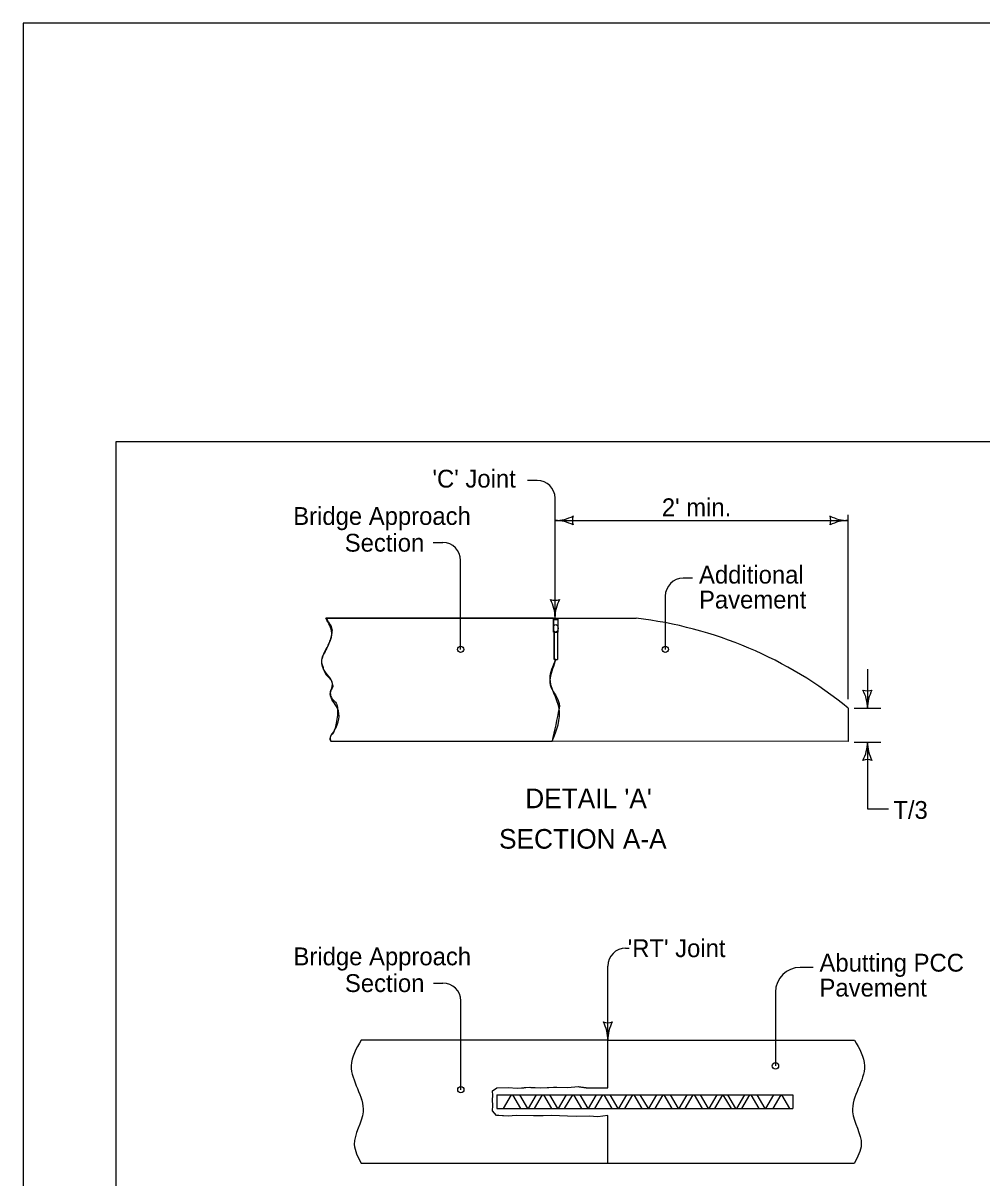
# Model space of a CAD drawing. Extents: x -2135039 to -2131695, y -2139150 to -2136566.
# Drawn here: x -2135039 to -2133963, y -2137862 to -2136566 of the extents above; entities that cross this region are included whole.
import ezdxf

# ---------------------------------------------------------------- set-up
doc = ezdxf.new("R2010")
doc.units = 0
for name, color, linetype in [('dsnCellElements', 7, 'Continuous'), ('dsnDOTLogo', 7, 'Continuous'), ('Level 1', 7, 'Continuous'), ('Level 2', 7, 'Continuous'), ('Level 3', 7, 'Continuous')]:
    doc.layers.add(name, color=color, linetype=linetype)

msp = doc.modelspace()

# ---------------------------------------------------------------- linework, layer by layer
at = {"layer": 'dsnCellElements'}
msp.add_circle((-2134194.9, -2137736.7), 3.54, dxfattribs=at)
at = {"layer": 'dsnDOTLogo'}
msp.add_lwpolyline([(-2135038.9, -2139150.4), (-2131694.9, -2139150.4), (-2131694.9, -2136566.4), (-2135038.9, -2136566.4)], close=True, dxfattribs=at)
at = {"layer": 'Level 1'}
msp.add_lwpolyline([(-2134934.4, -2137035.9), (-2131799.4, -2137035.9), (-2131799.4, -2139045.9), (-2134934.4, -2139045.9)], close=True, dxfattribs=at)
at = {"layer": 'Level 2'}
for p, q in [((-2134462.2, -2137079.6), (-2134473, -2137079.6)), ((-2134442.2, -2137233.7), (-2134442.2, -2137099.6)), ((-2134113.3, -2137325), (-2134113.3, -2137118.1)), ((-2134442.2, -2137124.6), (-2134113.3, -2137124.6)), ((-2134578.9, -2137149.4), (-2134568.1, -2137149.4)), ((-2134548.1, -2137269.3), (-2134548.1, -2137169.4)), ((-2134287.9, -2137189.4), (-2134298.5, -2137189.4)), ((-2134318.5, -2137209.4), (-2134318.5, -2137269.3)), ((-2134699.3, -2137234.3), (-2134441.4, -2137234.3)), ((-2134687.2, -2137234.3), (-2134699.3, -2137234.3)), ((-2134699.3, -2137234.3), (-2134697.4, -2137236.9)), ((-2134652.1, -2137234.3), (-2134685.7, -2137234.3)), ((-2134617, -2137234.3), (-2134650.5, -2137234.3)), ((-2134581.8, -2137234.3), (-2134615.4, -2137234.3)), ((-2134511.6, -2137234.3), (-2134545.2, -2137234.3)), ((-2134476.5, -2137234.3), (-2134510.1, -2137234.3)), ((-2134444, -2137234.3), (-2134475, -2137234.3)), ((-2134444, -2137234.3), (-2134444, -2137249.9)), ((-2134441.4, -2137234.3), (-2134351.1, -2137234.3)), ((-2134438.8, -2137249.9), (-2134438.8, -2137234.3)), ((-2134444, -2137235.9), (-2134438.8, -2137235.9)), ((-2134444, -2137249.9), (-2134438.8, -2137249.9)), ((-2134443.1, -2137249.9), (-2134444, -2137249.9)), ((-2134443.1, -2137249.9), (-2134443.1, -2137280.8)), ((-2134443.1, -2137280.8), (-2134443.1, -2137249.9)), ((-2134439.6, -2137249.9), (-2134439.6, -2137280.8)), ((-2134443.1, -2137280.8), (-2134439.6, -2137280.8)), ((-2134441.4, -2137280.8), (-2134443.1, -2137280.8)), ((-2134091.7, -2137291.5), (-2134091.7, -2137335.3)), ((-2134113.3, -2137335.3), (-2134113.3, -2137372.6)), ((-2134106.7, -2137335.3), (-2134076.7, -2137335.3)), ((-2134113.3, -2137372.6), (-2134693.9, -2137372.2)), ((-2134693.9, -2137372.2), (-2134445.5, -2137372.4)), ((-2134106.7, -2137373.5), (-2134076.7, -2137373.5)), ((-2134091.7, -2137373.5), (-2134091.7, -2137448.1)), ((-2134091.7, -2137448.1), (-2134068.2, -2137448.1)), ((-2134363, -2137604.6), (-2134359.1, -2137604.6)), ((-2134383, -2137707.7), (-2134383, -2137624.6)), ((-2134152.6, -2137626.2), (-2134167.2, -2137626.2)), ((-2134578.6, -2137643.7), (-2134567.9, -2137643.7)), ((-2134194.9, -2137653.9), (-2134194.9, -2137736.7)), ((-2134547.9, -2137763.5), (-2134547.9, -2137663.7)), ((-2134383, -2137707.7), (-2134659.6, -2137707.7)), ((-2134383, -2137707.7), (-2134106.4, -2137707.7)), ((-2134383, -2137761.5), (-2134383, -2137707.7)), ((-2134383, -2137761.5), (-2134383, -2137707.7)), ((-2134507.4, -2137769.1), (-2134175.5, -2137769.1)), ((-2134507.4, -2137769.1), (-2134507.4, -2137784.6)), ((-2134175.5, -2137769.1), (-2134175.5, -2137784.6)), ((-2134507.4, -2137784.6), (-2134175.5, -2137784.6)), ((-2134383, -2137846), (-2134383, -2137792.3)), ((-2134383, -2137846), (-2134383, -2137792.3)), ((-2134659.6, -2137846), (-2134374, -2137846)), ((-2134651.6, -2137846), (-2134651.6, -2137846)), ((-2134651.6, -2137846), (-2134618, -2137846)), ((-2134374, -2137846), (-2134106.4, -2137846))]:
    msp.add_line(p, q, dxfattribs=at)
for points in [[(-2134687.2, -2137234.3), (-2134687.2, -2137234.3)], [(-2134685.7, -2137234.3), (-2134685.7, -2137234.3)], [(-2134652.1, -2137234.3), (-2134652.1, -2137234.3)], [(-2134650.5, -2137234.3), (-2134650.5, -2137234.3)], [(-2134617, -2137234.3), (-2134617, -2137234.3)], [(-2134615.4, -2137234.3), (-2134615.4, -2137234.3)], [(-2134581.8, -2137234.3), (-2134581.8, -2137234.3)], [(-2134546.7, -2137234.3), (-2134548.1, -2137234.3), (-2134580.3, -2137234.3)], [(-2134580.3, -2137234.3), (-2134580.3, -2137234.3)], [(-2134546.7, -2137234.3), (-2134546.7, -2137234.3)], [(-2134545.2, -2137234.3), (-2134545.2, -2137234.3)], [(-2134511.6, -2137234.3), (-2134511.6, -2137234.3)], [(-2134510.1, -2137234.3), (-2134510.1, -2137234.3)], [(-2134476.5, -2137234.3), (-2134476.5, -2137234.3)], [(-2134475, -2137234.3), (-2134475, -2137234.3)], [(-2134444, -2137249.9), (-2134444, -2137235.9), (-2134444, -2137234.3)], [(-2134441.4, -2137280.8), (-2134441.4, -2137280.8)], [(-2134383, -2137707.7), (-2134468.4, -2137707.7), (-2134547.9, -2137707.7), (-2134605.4, -2137707.7), (-2134659.6, -2137707.7)], [(-2134383, -2137707.7), (-2134383, -2137707.7)], [(-2134507.7, -2137792.2), (-2134512.2, -2137787.2), (-2134511.9, -2137781), (-2134512.3, -2137774.9), (-2134511.9, -2137769.8), (-2134512.5, -2137764.7), (-2134507.6, -2137761.5)], [(-2134507.7, -2137792.2), (-2134512.2, -2137787.2), (-2134511.9, -2137781), (-2134512.3, -2137774.9), (-2134511.9, -2137769.8), (-2134512.5, -2137764.7), (-2134507.6, -2137761.5)], [(-2134507.6, -2137761.5), (-2134494.9, -2137760.9), (-2134484.6, -2137761.6), (-2134470.6, -2137760.7), (-2134458, -2137761.4), (-2134440.3, -2137760.5), (-2134427.9, -2137760.8), (-2134416.1, -2137760), (-2134404.4, -2137761.5), (-2134392.6, -2137761.4), (-2134382.9, -2137761.5)], [(-2134507.6, -2137761.5), (-2134494.9, -2137760.9), (-2134484.6, -2137761.6), (-2134479.9, -2137761.3), (-2134479.9, -2137761.3)], [(-2134475.1, -2137761), (-2134475.1, -2137761), (-2134470.6, -2137760.7), (-2134469.5, -2137760.8), (-2134469.5, -2137760.8), (-2134458, -2137761.4), (-2134443.9, -2137760.7), (-2134443.9, -2137760.7)], [(-2134440.5, -2137760.5), (-2134440.5, -2137760.5), (-2134440.3, -2137760.5), (-2134427.9, -2137760.8), (-2134416.1, -2137760), (-2134415.1, -2137760.2), (-2134415.1, -2137760.2), (-2134409.7, -2137760.8), (-2134409.3, -2137760.9)], [(-2134409.3, -2137760.9), (-2134409.3, -2137760.9)], [(-2134404.6, -2137761.5), (-2134404.4, -2137761.5), (-2134392.6, -2137761.4), (-2134383, -2137761.5)], [(-2134404.6, -2137761.5), (-2134404.6, -2137761.5)], [(-2134383, -2137761.5), (-2134383, -2137761.5)], [(-2134660.3, -2137774.3), (-2134660.4, -2137774.3)], [(-2134500, -2137784.6), (-2134491, -2137769.1)], [(-2134490, -2137769.1), (-2134481.1, -2137784.6)], [(-2134482.1, -2137769.1), (-2134473.1, -2137784.6)], [(-2134472.1, -2137784.6), (-2134463.1, -2137769.1)], [(-2134465.2, -2137784.6), (-2134456.2, -2137769.1)], [(-2134455.2, -2137769.1), (-2134446.2, -2137784.6)], [(-2134448.3, -2137769.1), (-2134439.3, -2137784.6)], [(-2134438.3, -2137784.6), (-2134429.3, -2137769.1)], [(-2134431.4, -2137784.6), (-2134422.4, -2137769.1)], [(-2134421.4, -2137769.1), (-2134412.4, -2137784.6)], [(-2134414.5, -2137769.1), (-2134405.5, -2137784.6)], [(-2134404.5, -2137784.6), (-2134395.5, -2137769.1)], [(-2134397.6, -2137784.6), (-2134388.6, -2137769.1)], [(-2134387.6, -2137769.1), (-2134378.6, -2137784.6)], [(-2134380.7, -2137769.1), (-2134371.7, -2137784.6)], [(-2134370.7, -2137784.6), (-2134361.7, -2137769.1)], [(-2134363.8, -2137784.6), (-2134354.8, -2137769.1)], [(-2134353.8, -2137769.1), (-2134344.8, -2137784.6)], [(-2134346.9, -2137769.1), (-2134337.9, -2137784.6)], [(-2134336.9, -2137784.6), (-2134327.9, -2137769.1)], [(-2134330, -2137784.6), (-2134321, -2137769.1)], [(-2134320, -2137769.1), (-2134311, -2137784.6)], [(-2134313.1, -2137769.1), (-2134304.1, -2137784.6)], [(-2134303.1, -2137784.6), (-2134294.1, -2137769.1)], [(-2134296.2, -2137784.6), (-2134287.2, -2137769.1)], [(-2134286.2, -2137769.1), (-2134277.2, -2137784.6)], [(-2134279.3, -2137769.1), (-2134270.3, -2137784.6)], [(-2134269.3, -2137784.6), (-2134260.3, -2137769.1)], [(-2134254.4, -2137769.1), (-2134263.4, -2137784.6)], [(-2134244.4, -2137784.6), (-2134253.4, -2137769.1)], [(-2134239.5, -2137784.6), (-2134248.5, -2137769.1)], [(-2134229.5, -2137769.1), (-2134238.5, -2137784.6)], [(-2134232.6, -2137784.6), (-2134223.6, -2137769.1)], [(-2134222.6, -2137769.1), (-2134213.6, -2137784.6)], [(-2134215.7, -2137769.1), (-2134206.7, -2137784.6)], [(-2134205.7, -2137784.6), (-2134196.7, -2137769.1)], [(-2134188.8, -2137769.1), (-2134197.8, -2137784.6)], [(-2134178.9, -2137784.6), (-2134187.8, -2137769.1)], [(-2134383, -2137792.3), (-2134394.2, -2137793.8), (-2134404, -2137793.2), (-2134418, -2137793.6), (-2134428.1, -2137793.2), (-2134446.2, -2137792.5), (-2134464, -2137792.9), (-2134485.7, -2137792.5), (-2134494.9, -2137793), (-2134507.7, -2137792.2)], [(-2134466.4, -2137792.9), (-2134466.4, -2137792.9), (-2134485.7, -2137792.5), (-2134494.9, -2137793), (-2134505.1, -2137792.4), (-2134505.1, -2137792.4), (-2134507.7, -2137792.2)], [(-2134383, -2137792.3), (-2134394.2, -2137793.8), (-2134404, -2137793.2), (-2134418, -2137793.6), (-2134428.1, -2137793.2), (-2134446.2, -2137792.5), (-2134455.5, -2137792.7), (-2134455.5, -2137792.7), (-2134461.5, -2137792.9), (-2134461.5, -2137792.9)], [(-2134659.6, -2137846), (-2134653.1, -2137846), (-2134653.1, -2137846)], [(-2134616.5, -2137846), (-2134616.5, -2137846)], [(-2134616.5, -2137846), (-2134604.9, -2137846), (-2134582.9, -2137846), (-2134582.9, -2137846)], [(-2134581.4, -2137846), (-2134581.4, -2137846), (-2134547.8, -2137846), (-2134547.8, -2137846)], [(-2134546.3, -2137846), (-2134546.3, -2137846), (-2134512.7, -2137846), (-2134512.7, -2137846)], [(-2134511.2, -2137846), (-2134511.2, -2137846), (-2134477.6, -2137846), (-2134477.6, -2137846)], [(-2134476.1, -2137846), (-2134476.1, -2137846), (-2134467.9, -2137846), (-2134442.5, -2137846), (-2134442.5, -2137846)], [(-2134441, -2137846), (-2134441, -2137846), (-2134407.4, -2137846), (-2134407.4, -2137846)], [(-2134405.9, -2137846), (-2134405.9, -2137846), (-2134383, -2137846)], [(-2134383, -2137846), (-2134383, -2137846)]]:
    msp.add_lwpolyline(points, dxfattribs=at)
for centre in [(-2134548.1, -2137269.3), (-2134548.1, -2137269.3), (-2134318.5, -2137269.3), (-2134547.9, -2137763.5), (-2134547.9, -2137763.5)]:
    msp.add_circle(centre, 3.5, dxfattribs=at)
for centre, radius, start, end in [((-2134462.2, -2137099.6), 20, 0, 90), ((-2134442.2, -2137081.5), 43.2, 270, 298.0725), ((-2134442.2, -2137081.5), 43.2, 270, 298.0725), ((-2134442.2, -2137167.8), 43.2, 61.9275, 90), ((-2134442.2, -2137167.8), 43.2, 61.9275, 90), ((-2134406, -2137124.6), 16.7, 162.2666, 197.7334), ((-2134406, -2137124.6), 16.7, 162.2666, 197.7334), ((-2134149.5, -2137124.6), 16.7, 342.2666, 17.7333), ((-2134113.3, -2137081.5), 43.2, 241.9275, 270), ((-2134113.3, -2137167.8), 43.2, 90, 118.0725), ((-2134568.1, -2137169.4), 20, 0, 90), ((-2134298.5, -2137209.4), 20, 90, 180), ((-2134442.2, -2137197.5), 16.7, 252.2666, 287.7333), ((-2134485.4, -2137233.7), 43.2, 360, 28.0725), ((-2134399.1, -2137233.7), 43.2, 151.9275, 180), ((-2134404.5, -2137690.6), 459.4, 50.6582, 83.3286), ((-2134091.7, -2137299.1), 16.7, 252.2666, 287.7333), ((-2134134.9, -2137335.3), 43.2, 360, 28.0725), ((-2134048.5, -2137335.3), 43.2, 151.9275, 180), ((-2134134.9, -2137373.5), 43.2, 331.9275, 360), ((-2134048.5, -2137373.5), 43.2, 180, 208.0725), ((-2134091.7, -2137409.7), 16.7, 72.2666, 107.7334), ((-2134363, -2137624.6), 20, 90, 180), ((-2134167.2, -2137653.9), 27.7, 90, 180), ((-2134567.9, -2137663.7), 20, 0, 90), ((-2134383, -2137671.5), 16.7, 252.2666, 287.7333), ((-2134426.1, -2137707.7), 43.2, 360, 28.0725), ((-2134339.8, -2137707.7), 43.2, 151.9275, 180), ((-2134339.8, -2137707.7), 43.2, 179.9993, 180)]:
    msp.add_arc(centre, radius, start, end, dxfattribs=at)
msp.add_ellipse((-2134441.4, -2137245.6), major_axis=(0, 4.37), ratio=0.6, dxfattribs=at)
for points in [[(-2134693.8, -2137372.3), (-2134694.3, -2137370.6), (-2134689.6, -2137359.9), (-2134686.3, -2137335.3), (-2134694.3, -2137319.2), (-2134691.9, -2137308.4), (-2134701.9, -2137291.5), (-2134703.5, -2137279.2), (-2134698.9, -2137269.2), (-2134692.7, -2137250.8), (-2134699.3, -2137234.3)], [(-2134441.4, -2137280.8), (-2134447.7, -2137301.8), (-2134447.9, -2137302.8), (-2134448.1, -2137303.9), (-2134448.1, -2137306), (-2134447.2, -2137310.1), (-2134443, -2137318.4), (-2134438.6, -2137326.8), (-2134437.5, -2137331), (-2134437.3, -2137333.1), (-2134437.4, -2137334.2), (-2134437.6, -2137335.3), (-2134445.5, -2137372.4)], [(-2134445.5, -2137372.4), (-2134437.6, -2137335.3), (-2134447.7, -2137301.8), (-2134441.4, -2137280.8)], [(-2134659.6, -2137707.7), (-2134670.9, -2137736.5), (-2134657.5, -2137788.3), (-2134667.4, -2137824.9), (-2134659.6, -2137846)], [(-2134659.6, -2137707.7), (-2134670.9, -2137736.5), (-2134657.5, -2137788.3), (-2134667.4, -2137824.9), (-2134659.6, -2137846)], [(-2134106.4, -2137707.7), (-2134095, -2137736.5), (-2134108.4, -2137788.3), (-2134098.6, -2137824.9), (-2134106.4, -2137846)]]:
    msp.add_spline(points, degree=3, dxfattribs=at)
for points, degree in [([(-2134685.7, -2137234.3), (-2134686.1, -2137234.3), (-2134686.7, -2137234.3), (-2134687.2, -2137234.3)], 2), ([(-2134650.5, -2137234.3), (-2134651, -2137234.3), (-2134651.5, -2137234.3), (-2134652.1, -2137234.3)], 2), ([(-2134615.4, -2137234.3), (-2134615.9, -2137234.3), (-2134616.4, -2137234.3), (-2134617, -2137234.3)], 2), ([(-2134580.3, -2137234.3), (-2134580.8, -2137234.3), (-2134581.3, -2137234.3), (-2134581.8, -2137234.3)], 2), ([(-2134545.2, -2137234.3), (-2134545.7, -2137234.3), (-2134546.2, -2137234.3), (-2134546.7, -2137234.3)], 2), ([(-2134510.1, -2137234.3), (-2134510.6, -2137234.3), (-2134511.1, -2137234.3), (-2134511.6, -2137234.3)], 2), ([(-2134475, -2137234.3), (-2134475.5, -2137234.3), (-2134476, -2137234.3), (-2134476.5, -2137234.3)], 2), ([(-2134695.9, -2137239.1), (-2134693.5, -2137242.9), (-2134692, -2137246.8), (-2134692.7, -2137250.8), (-2134693.8, -2137256.9), (-2134696.4, -2137263.1), (-2134698.9, -2137269.2), (-2134700.2, -2137272.7), (-2134702.4, -2137275.8), (-2134703.5, -2137279.2), (-2134704.7, -2137283.1), (-2134703.1, -2137287.6), (-2134701.9, -2137291.5), (-2134700, -2137297.6), (-2134693.5, -2137302.3), (-2134691.9, -2137308.4), (-2134691.1, -2137311.8), (-2134694.8, -2137315.7), (-2134694.3, -2137319.2), (-2134693.3, -2137324.8), (-2134686.5, -2137329.6), (-2134686.3, -2137335.3), (-2134686.1, -2137343.1), (-2134687.5, -2137352.1), (-2134689.6, -2137359.9), (-2134690.7, -2137363.6), (-2134695.1, -2137366.8), (-2134694.3, -2137370.6), (-2134694.1, -2137371.2), (-2134694, -2137371.7), (-2134693.9, -2137372.2)], 3), ([(-2134697.4, -2137236.9), (-2134697.1, -2137237.1), (-2134696.5, -2137237.8), (-2134696.1, -2137238.6), (-2134695.9, -2137239.1)], 3), ([(-2134479.9, -2137761.3), (-2134479.2, -2137761.3), (-2134478.4, -2137761.2), (-2134477.4, -2137761.2), (-2134476.1, -2137761.1), (-2134475.1, -2137761)], 3), ([(-2134443.9, -2137760.7), (-2134443.3, -2137760.7), (-2134442.6, -2137760.6), (-2134441.3, -2137760.5), (-2134440.5, -2137760.5)], 3), ([(-2134409.3, -2137760.9), (-2134408.4, -2137761), (-2134407.7, -2137761.1), (-2134406.8, -2137761.2), (-2134405.9, -2137761.3), (-2134404.6, -2137761.5)], 3), ([(-2134461.5, -2137792.9), (-2134463, -2137792.9), (-2134464, -2137792.9), (-2134465.5, -2137792.9), (-2134466.4, -2137792.9)], 3), ([(-2134653.1, -2137846), (-2134652.6, -2137845.9), (-2134652.1, -2137845.9), (-2134651.6, -2137846)], 2), ([(-2134618, -2137846), (-2134617.5, -2137845.9), (-2134617, -2137845.9), (-2134616.5, -2137846)], 2), ([(-2134618, -2137846), (-2134617.5, -2137845.9), (-2134617, -2137845.9), (-2134616.5, -2137846)], 2), ([(-2134582.9, -2137846), (-2134582.4, -2137845.9), (-2134581.8, -2137845.9), (-2134581.4, -2137846)], 2), ([(-2134547.8, -2137846), (-2134547.3, -2137845.9), (-2134546.7, -2137845.9), (-2134546.3, -2137846)], 2), ([(-2134512.7, -2137846), (-2134512.2, -2137845.9), (-2134511.6, -2137845.9), (-2134511.2, -2137846)], 2), ([(-2134477.6, -2137846), (-2134477.1, -2137845.9), (-2134476.5, -2137845.9), (-2134476.1, -2137846)], 2), ([(-2134442.5, -2137846), (-2134442, -2137845.9), (-2134441.4, -2137845.9), (-2134441, -2137846)], 2), ([(-2134407.4, -2137846), (-2134406.8, -2137845.9), (-2134406.3, -2137845.9), (-2134405.9, -2137846)], 2)]:
    msp.add_open_spline(points, degree=degree, dxfattribs=at)

# ---------------------------------------------------------------- texts
at = {"layer": 'Level 3'}
for s, height, p in [("'C' Joint", 20, (-2134579.7, -2137087.7)), ("2' min.", 20, (-2134322.4, -2137119.8)), ('Bridge Approach', 20, (-2134735.9, -2137129.6)), ('Section', 20, (-2134678.1, -2137159.6)), ('Additional ', 20, (-2134280.7, -2137195.4)), ('Pavement', 20, (-2134280.7, -2137223.4)), ("DETAIL 'A'", 22, (-2134475.6, -2137447.5)), ('T/3', 20, (-2134062.7, -2137459.5)), ('SECTION A-A', 22, (-2134505, -2137492.9)), ("'RT' Joint", 20, (-2134360.7, -2137614.6)), ('Bridge Approach', 20, (-2134735.6, -2137623.8)), ('Abutting PCC', 20, (-2134145.5, -2137630.9)), ('Section', 20, (-2134677.9, -2137653.8)), ('Pavement', 20, (-2134145.5, -2137658.9))]:
    msp.add_text(s, height=height, dxfattribs=at).set_placement(p)

doc.saveas('drawing.dxf')
